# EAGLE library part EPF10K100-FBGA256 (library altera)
EPF10K100 FLEX 10K family
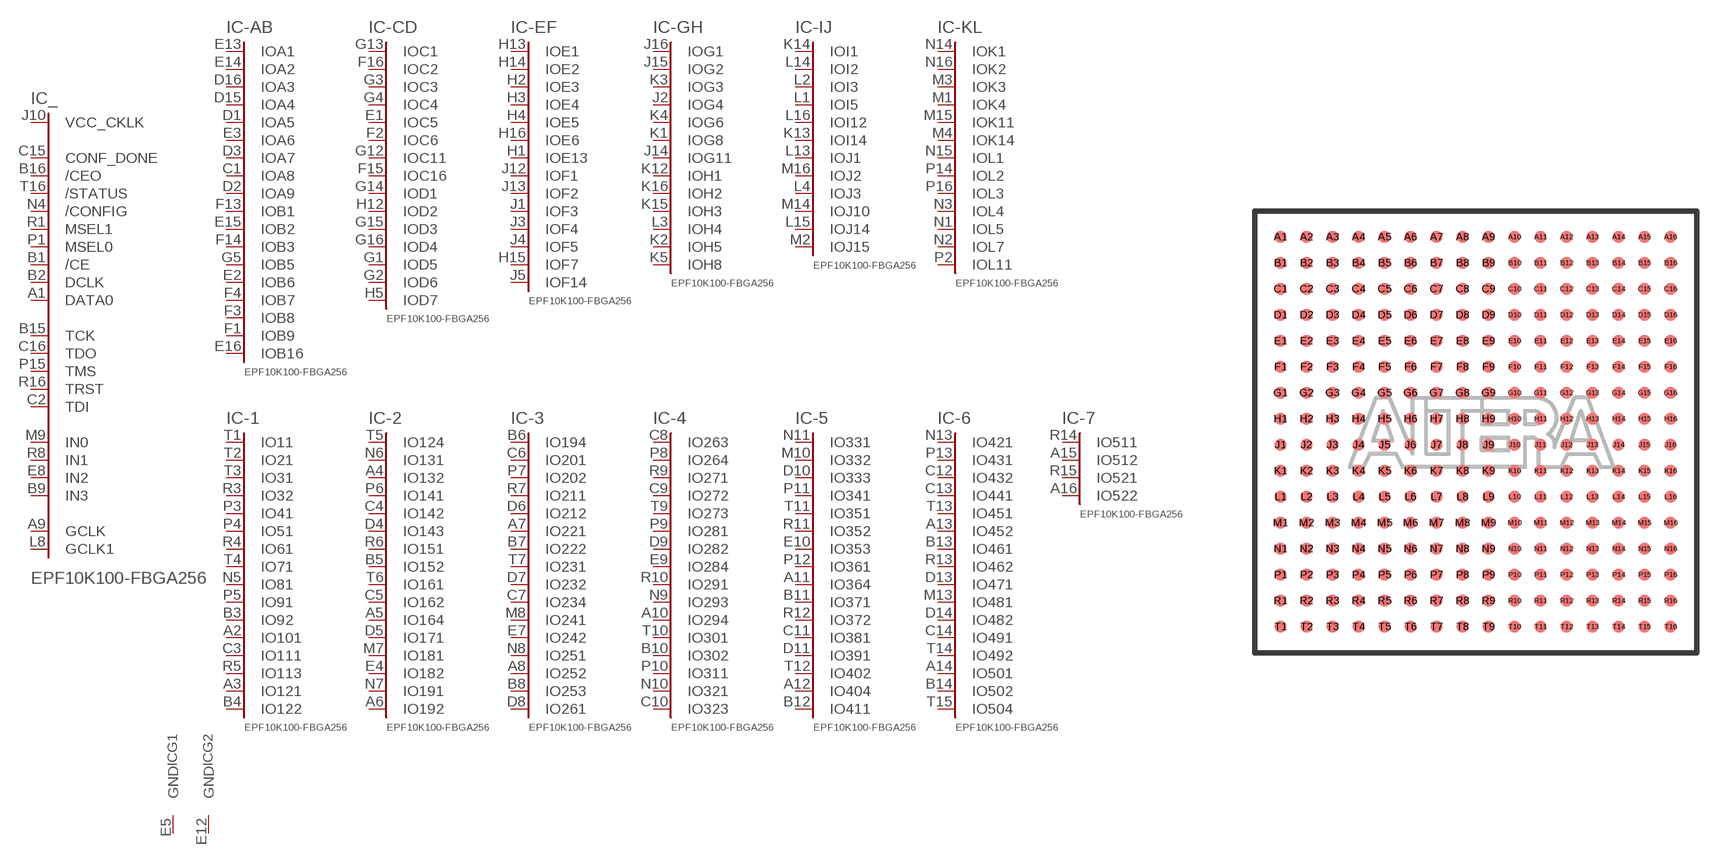
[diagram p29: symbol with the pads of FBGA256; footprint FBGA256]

Designator prefix IC; gates _=100F256C -1=122-256 -2=192-256 -3=261-256 -4=323-256 -5=411-256 -6=504-256 -7=522-256 -AB=AB-256 -CD=CD-256 -EF=EF-256 -GH=GH-256 -IJ=IJ-256 -KL=KL-256 G1=GND G2=GND G3=GND G4=GND G5=GND G6=GND G7=GND G8=GND G9=GND G10=GND G11=GND G12=GND G13=GND G14=GND G15=GND G16=GND G17=GND G18=GND V1=VCCINT V2=VCCINT V3=VCCINT V4=VCCINT V5=VCCINT V6=VCCINT V7=VCCINT V8=VCCINT V9=VCCINT V10=VCCINT V11=VCCINT V12=VCCINT V13=VCCINT V14=VCCINT V15=VCCINT V16=VCCINT V17=VCCINT VO1=VCCIO VO2=VCCIO VO3=VCCIO VO4=VCCIO VO5=VCCIO VO6=VCCIO VO7=VCCIO VO8=VCCIO VO9=VCCIO VO10=VCCIO VO11=VCCIO VO12=VCCIO VO13=VCCIO VO14=VCCIO VO15=VCCIO

## EPF10K100-FBGA256 (MPN: EPF10K100EFC256-1; OC_FARNELL: unknown; OC_NEWARK: 51R8810)  [FBGA256]
A1  _:DATA0  in
A2  -1:IO101
A3  -1:IO121
A4  -2:IO132
A5  -2:IO164
A6  -2:IO192
A7  -3:IO221
A8  -3:IO252
A9  _:GCLK  in
A10  -4:IO294
A11  -5:IO364
A12  -5:IO404
A13  -6:IO452
A14  -6:IO501
A15  -7:IO512
A16  -7:IO522
B1  _:/CE  in
B2  _:DCLK  in
B3  -1:IO92
B4  -1:IO122
B5  -2:IO152
B6  -3:IO194
B7  -3:IO222
B8  -3:IO253
B9  _:IN3  in
B10  -4:IO302
B11  -5:IO371
B12  -5:IO411
B13  -6:IO461
B14  -6:IO502
B15  _:TCK
B16  _:/CEO  in
C1  -AB:IOA8
C2  _:TDI
C3  -1:IO111
C4  -2:IO142
C5  -2:IO162
C6  -3:IO201
C7  -3:IO234
C8  -4:IO263
C9  -4:IO272
C10  -4:IO323
C11  -5:IO381
C12  -6:IO432
C13  -6:IO441
C14  -6:IO491
C15  _:CONF_DONE  in
C16  _:TDO
D1  -AB:IOA5
D2  -AB:IOA9
D3  -AB:IOA7
D4  -2:IO143
D5  -2:IO171
D6  -3:IO212
D7  -3:IO232
D8  -3:IO261
D9  -4:IO282
D10  -5:IO333
D11  -5:IO391
D12  VO1:VCCIO  pwr
D13  -6:IO471
D14  -6:IO482
D15  -AB:IOA4
D16  -AB:IOA3
E1  -CD:IOC5
E2  -AB:IOB6
E3  -AB:IOA6
E4  -2:IO182
E5  G1:GND  pwr
E6  VO2:VCCIO  pwr
E7  -3:IO242
E8  _:IN2  in
E9  -4:IO284
E10  -5:IO353
E11  V1:VCC  pwr
E12  G2:GND  pwr
E13  -AB:IOA1
E14  -AB:IOA2
E15  -AB:IOB2
E16  -AB:IOB16
F1  -AB:IOB9
F2  -CD:IOC6
F3  -AB:IOB8
F4  -AB:IOB7
F5  V2:VCC  pwr
F6  G3:GND  pwr
F7  V3:VCC  pwr
F8  VO3:VCCIO  pwr
F9  V4:VCC  pwr
F10  VO4:VCCIO  pwr
F11  G4:GND  pwr
F12  V5:VCC  pwr
F13  -AB:IOB1
F14  -AB:IOB3
F15  -CD:IOC16
F16  -CD:IOC2
G1  -CD:IOD5
G2  -CD:IOD6
G3  -CD:IOC3
G4  -CD:IOC4
G5  -AB:IOB5
G6  VO5:VCCIO  pwr
G7  G5:GND  pwr
G8  VO6:VCCIO  pwr
G9  G6:GND  pwr
G10  G7:GND  pwr
G11  VO7:VCCIO  pwr
G12  -CD:IOC11
G13  -CD:IOC1
G14  -CD:IOD1
G15  -CD:IOD3
G16  -CD:IOD4
H1  -EF:IOE13
H2  -EF:IOE3
H3  -EF:IOE4
H4  -EF:IOE5
H5  -CD:IOD7
H6  V6:VCC  pwr
H7  V7:VCC  pwr
H8  G8:GND  pwr
H9  G9:GND  pwr
H10  V8:VCC  pwr
H11  VO8:VCCIO  pwr
H12  -CD:IOD2
H13  -EF:IOE1
H14  -EF:IOE2
H15  -EF:IOF7
H16  -EF:IOE6
J1  -EF:IOF3
J2  -GH:IOG4
J3  -EF:IOF4
J4  -EF:IOF5
J5  -EF:IOF14
J6  VO9:VCCIO  pwr
J7  V9:VCC  pwr
J8  G10:GND  pwr
J9  G11:GND  pwr
J10  _:VCC_CKLK  pas
J11  V10:VCC  pwr
J12  -EF:IOF1
J13  -EF:IOF2
J14  -GH:IOG11
J15  -GH:IOG2
J16  -GH:IOG1
K1  -GH:IOG8
K2  -GH:IOH5
K3  -GH:IOG3
K4  -GH:IOG6
K5  -GH:IOH8
K6  VO10:VCCIO  pwr
K7  G12:GND  pwr
K8  VO11:VCCIO  pwr
K9  V11:VCC  pwr
K10  G13:GND  pwr
K11  VO12:VCCIO  pwr
K12  -GH:IOH1
K13  -IJ:IOI14
K14  -IJ:IOI1
K15  -GH:IOH3
K16  -GH:IOH2
L1  -IJ:IOI5
L2  -IJ:IOI3
L3  -GH:IOH4
L4  -IJ:IOJ3
L5  V12:VCC  pwr
L6  G14:GND  pwr
L7  V13:VCC  pwr
L8  _:GCLK1  in
L9  V14:VCC  pwr
L10  VO13:VCCIO  pwr
L11  G15:GND  pwr
L12  V15:VCC  pwr
L13  -IJ:IOJ1
L14  -IJ:IOI2
L15  -IJ:IOJ14
L16  -IJ:IOI12
M1  -KL:IOK4
M2  -IJ:IOJ15
M3  -KL:IOK3
M4  -KL:IOK14
M5  G16:GND  pwr
M6  VO14:VCCIO  pwr
M7  -2:IO181
M8  -3:IO241
M9  _:IN0  in
M10  -5:IO332
M11  V16:VCC  pwr
M12  G17:GND  pwr
M13  -6:IO481
M14  -IJ:IOJ10
M15  -KL:IOK11
M16  -IJ:IOJ2
N1  -KL:IOL5
N2  -KL:IOL7
N3  -KL:IOL4
N4  _:/CONFIG  in
N5  -1:IO81
N6  -2:IO131
N7  -2:IO191
N8  -3:IO251
N9  -4:IO293
N10  -4:IO321
N11  -5:IO331
N12  VO15:VCCIO  pwr
N13  -6:IO421
N14  -KL:IOK1
N15  -KL:IOL1
N16  -KL:IOK2
P1  _:MSEL0  in
P2  -KL:IOL11
P3  -1:IO41
P4  -1:IO51
P5  -1:IO91
P6  -2:IO141
P7  -3:IO202
P8  -4:IO264
P9  -4:IO281
P10  -4:IO311
P11  -5:IO341
P12  -5:IO361
P13  -6:IO431
P14  -KL:IOL2
P15  _:TMS
P16  -KL:IOL3
R1  _:MSEL1  in
R2  V17:VCC  pwr
R3  -1:IO32
R4  -1:IO61
R5  -1:IO113
R6  -2:IO151
R7  -3:IO211
R8  _:IN1  in
R9  -4:IO271
R10  -4:IO291
R11  -5:IO352
R12  -5:IO372
R13  -6:IO462
R14  -7:IO511
R15  -7:IO521
R16  _:TRST
T1  -1:IO11
T2  -1:IO21
T3  -1:IO31
T4  -1:IO71
T5  -2:IO124
T6  -2:IO161
T7  -3:IO231
T8  G18:GND  pwr
T9  -4:IO273
T10  -4:IO301
T11  -5:IO351
T12  -5:IO402
T13  -6:IO451
T14  -6:IO492
T15  -6:IO504
T16  _:/STATUS  in

## Footprint FBGA256 (pad centres in mm)
Fine Ball Grid Array
smd 0.45 x 0.45: A1 -7.5,7.5; A2 -6.5,7.5; A3 -5.5,7.5; A4 -4.5,7.5; A5 -3.5,7.5; A6 -2.5,7.5; A7 -1.5,7.5; A8 -0.5,7.5; A9 0.5,7.5; A10 1.5,7.5; A11 2.5,7.5; A12 3.5,7.5; A13 4.5,7.5; A14 5.5,7.5; A15 6.5,7.5; A16 7.5,7.5; B1 -7.5,6.5; B2 -6.5,6.5; B3 -5.5,6.5; B4 -4.5,6.5; B5 -3.5,6.5; B6 -2.5,6.5; B7 -1.5,6.5; B8 -0.5,6.5; B9 0.5,6.5; B10 1.5,6.5; B11 2.5,6.5; B12 3.5,6.5; B13 4.5,6.5; B14 5.5,6.5; B15 6.5,6.5; B16 7.5,6.5; C1 -7.5,5.5; C2 -6.5,5.5; C3 -5.5,5.5; C4 -4.5,5.5; C5 -3.5,5.5; C6 -2.5,5.5; C7 -1.5,5.5; C8 -0.5,5.5; C9 0.5,5.5; C10 1.5,5.5; C11 2.5,5.5; C12 3.5,5.5; C13 4.5,5.5; C14 5.5,5.5; C15 6.5,5.5; C16 7.5,5.5; D1 -7.5,4.5; D2 -6.5,4.5; D3 -5.5,4.5; D4 -4.5,4.5; D5 -3.5,4.5; D6 -2.5,4.5; D7 -1.5,4.5; D8 -0.5,4.5; D9 0.5,4.5; D10 1.5,4.5; D11 2.5,4.5; D12 3.5,4.5; D13 4.5,4.5; D14 5.5,4.5; D15 6.5,4.5; D16 7.5,4.5; E1 -7.5,3.5; E2 -6.5,3.5; E3 -5.5,3.5; E4 -4.5,3.5; E5 -3.5,3.5; E6 -2.5,3.5; E7 -1.5,3.5; E8 -0.5,3.5; E9 0.5,3.5; E10 1.5,3.5; E11 2.5,3.5; E12 3.5,3.5; E13 4.5,3.5; E14 5.5,3.5; E15 6.5,3.5; E16 7.5,3.5; F1 -7.5,2.5; F2 -6.5,2.5; F3 -5.5,2.5; F4 -4.5,2.5; F5 -3.5,2.5; F6 -2.5,2.5; F7 -1.5,2.5; F8 -0.5,2.5; F9 0.5,2.5; F10 1.5,2.5; F11 2.5,2.5; F12 3.5,2.5; F13 4.5,2.5; F14 5.5,2.5; F15 6.5,2.5; F16 7.5,2.5; G1 -7.5,1.5; G2 -6.5,1.5; G3 -5.5,1.5; G4 -4.5,1.5; G5 -3.5,1.5; G6 -2.5,1.5; G7 -1.5,1.5; G8 -0.5,1.5; G9 0.5,1.5; G10 1.5,1.5; G11 2.5,1.5; G12 3.5,1.5; G13 4.5,1.5; G14 5.5,1.5; G15 6.5,1.5; G16 7.5,1.5; H1 -7.5,0.5; H2 -6.5,0.5; H3 -5.5,0.5; H4 -4.5,0.5; H5 -3.5,0.5; H6 -2.5,0.5; H7 -1.5,0.5; H8 -0.5,0.5; H9 0.5,0.5; H10 1.5,0.5; H11 2.5,0.5; H12 3.5,0.5; H13 4.5,0.5; H14 5.5,0.5; H15 6.5,0.5; H16 7.5,0.5; J1 -7.5,-0.5; J2 -6.5,-0.5; J3 -5.5,-0.5; J4 -4.5,-0.5; J5 -3.5,-0.5; J6 -2.5,-0.5; J7 -1.5,-0.5; J8 -0.5,-0.5; J9 0.5,-0.5; J10 1.5,-0.5; J11 2.5,-0.5; J12 3.5,-0.5; J13 4.5,-0.5; J14 5.5,-0.5; J15 6.5,-0.5; J16 7.5,-0.5; K1 -7.5,-1.5; K2 -6.5,-1.5; K3 -5.5,-1.5; K4 -4.5,-1.5; K5 -3.5,-1.5; K6 -2.5,-1.5; K7 -1.5,-1.5; K8 -0.5,-1.5; K9 0.5,-1.5; K10 1.5,-1.5; K11 2.5,-1.5; K12 3.5,-1.5; K13 4.5,-1.5; K14 5.5,-1.5; K15 6.5,-1.5; K16 7.5,-1.5; L1 -7.5,-2.5; L2 -6.5,-2.5; L3 -5.5,-2.5; L4 -4.5,-2.5; L5 -3.5,-2.5; L6 -2.5,-2.5; L7 -1.5,-2.5; L8 -0.5,-2.5; L9 0.5,-2.5; L10 1.5,-2.5; L11 2.5,-2.5; L12 3.5,-2.5; L13 4.5,-2.5; L14 5.5,-2.5; L15 6.5,-2.5; L16 7.5,-2.5; M1 -7.5,-3.5; M2 -6.5,-3.5; M3 -5.5,-3.5; M4 -4.5,-3.5; M5 -3.5,-3.5; M6 -2.5,-3.5; M7 -1.5,-3.5; M8 -0.5,-3.5; M9 0.5,-3.5; M10 1.5,-3.5; M11 2.5,-3.5; M12 3.5,-3.5; M13 4.5,-3.5; M14 5.5,-3.5; M15 6.5,-3.5; M16 7.5,-3.5; N1 -7.5,-4.5; N2 -6.5,-4.5; N3 -5.5,-4.5; N4 -4.5,-4.5; N5 -3.5,-4.5; N6 -2.5,-4.5; N7 -1.5,-4.5; N8 -0.5,-4.5; N9 0.5,-4.5; N10 1.5,-4.5; N11 2.5,-4.5; N12 3.5,-4.5; N13 4.5,-4.5; N14 5.5,-4.5; N15 6.5,-4.5; N16 7.5,-4.5; P1 -7.5,-5.5; P2 -6.5,-5.5; P3 -5.5,-5.5; P4 -4.5,-5.5; P5 -3.5,-5.5; P6 -2.5,-5.5; P7 -1.5,-5.5; P8 -0.5,-5.5; P9 0.5,-5.5; P10 1.5,-5.5; P11 2.5,-5.5; P12 3.5,-5.5; P13 4.5,-5.5; P14 5.5,-5.5; P15 6.5,-5.5; P16 7.5,-5.5; R1 -7.5,-6.5; R2 -6.5,-6.5; R3 -5.5,-6.5; R4 -4.5,-6.5; R5 -3.5,-6.5; R6 -2.5,-6.5; R7 -1.5,-6.5; R8 -0.5,-6.5; R9 0.5,-6.5; R10 1.5,-6.5; R11 2.5,-6.5; R12 3.5,-6.5; R13 4.5,-6.5; R14 5.5,-6.5; R15 6.5,-6.5; R16 7.5,-6.5; T1 -7.5,-7.5; T2 -6.5,-7.5; T3 -5.5,-7.5; T4 -4.5,-7.5; T5 -3.5,-7.5; T6 -2.5,-7.5; T7 -1.5,-7.5; T8 -0.5,-7.5; T9 0.5,-7.5; T10 1.5,-7.5; T11 2.5,-7.5; T12 3.5,-7.5; T13 4.5,-7.5; T14 5.5,-7.5; T15 6.5,-7.5; T16 7.5,-7.5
